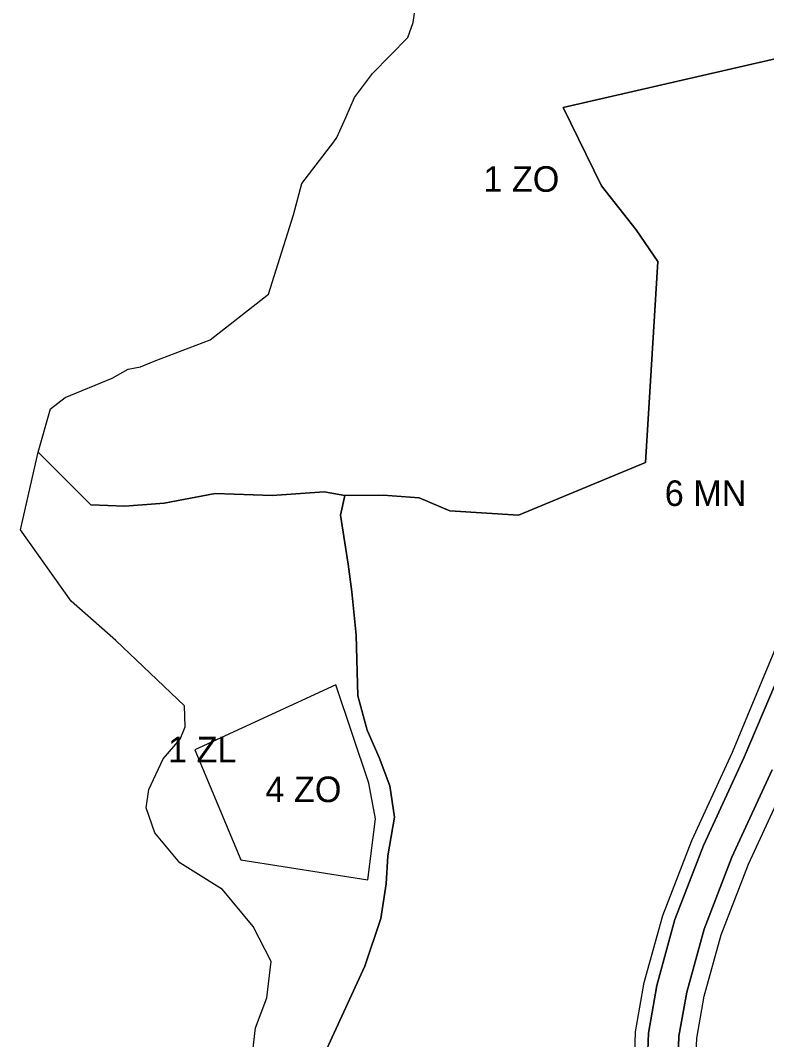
# Model space of a CAD drawing. Extents: x 7424258 to 7426021, y 5551671 to 5553193.
# Drawn here: x 7424719 to 7425010.8, y 5552254.6 to 5552653.2 of the extents above; entities that cross this region are included whole.
import ezdxf

# ---------------------------------------------------------------- set-up
doc = ezdxf.new("R2010")
doc.units = 0
for name, color, linetype in [('linie_rozgraniczajace', 7, 'Continuous'), ('linie_zabudowy_nieprzekraczalne', 7, 'Continuous'), ('oznaczenia_przeznaczen', 7, 'Continuous')]:
    doc.layers.add(name, color=color, linetype=linetype)

msp = doc.modelspace()

# ---------------------------------------------------------------- linework, layer by layer
at = {"layer": 'linie_rozgraniczajace'}
for points in [[(7425051.06, 5552646.66), (7424995.42, 5552633.88), (7424931.2, 5552619.13), (7424946.21, 5552588.55), (7424959.87, 5552571.29), (7424968.35, 5552558.94), (7424963.44, 5552480.3), (7424913.85, 5552459.68), (7424886.97, 5552461.47), (7424874.98, 5552466.54), (7424860.8, 5552467.57), (7424845.83, 5552467.4), (7424837.76, 5552468.8), (7424817.51, 5552467.42), (7424795.11, 5552468.2), (7424775.22, 5552464.46), (7424759.82, 5552463.2), (7424746.49, 5552463.77), (7424726, 5552484.37), (7424730.78, 5552501.26), (7424736.47, 5552505.78), (7424754.82, 5552513.35), (7424761.17, 5552516.77), (7424765.9, 5552517.79), (7424771.24, 5552520), (7424793.23, 5552528.28), (7424816.07, 5552546.19), (7424825.79, 5552577.17), (7424829.04, 5552589.49), (7424841.61, 5552605.76), (7424842.74, 5552607.38), (7424846.22, 5552615.24), (7424849.71, 5552623.09), (7424856.75, 5552632.4), (7424870.55, 5552646.47), (7424872.66, 5552652.39), (7424873.65, 5552659.77)], [(7424836.47, 5552245.91), (7424853.66, 5552283.41), (7424859.99, 5552302.04), (7424862.02, 5552315.51), (7424862.63, 5552326.5), (7424865.3, 5552341.64), (7424863.44, 5552353.82), (7424859.27, 5552364.91), (7424854.67, 5552375.64), (7424850.96, 5552389.13), (7424850.3, 5552412.81), (7424848.56, 5552429.74), (7424847.22, 5552440.55), (7424844.17, 5552459.66), (7424845.83, 5552467.4), (7424860.8, 5552467.57), (7424874.98, 5552466.54), (7424886.97, 5552461.47), (7424913.85, 5552459.68), (7424963.44, 5552480.3), (7424968.35, 5552558.94), (7424959.87, 5552571.29), (7424946.21, 5552588.55), (7424931.2, 5552619.13), (7424995.42, 5552633.88), (7425051.06, 5552646.66)], [(7424809.54, 5552246.79), (7424810.92, 5552259.2), (7424815.33, 5552270.93), (7424817.09, 5552285.18), (7424809.99, 5552298.89), (7424797.99, 5552313.35), (7424781.28, 5552323.8), (7424771.54, 5552335.48), (7424768.23, 5552345.3), (7424769.18, 5552352.42), (7424774.86, 5552364.48), (7424781.51, 5552372.14), (7424783.46, 5552376.91), (7424783.18, 5552385.11), (7424769.77, 5552397.94), (7424756.36, 5552410.77), (7424738.87, 5552426.09), (7424718.98, 5552453.98), (7424726, 5552484.37), (7424746.49, 5552463.77), (7424759.82, 5552463.2), (7424775.22, 5552464.46), (7424795.11, 5552468.2), (7424817.51, 5552467.42), (7424837.76, 5552468.8), (7424845.83, 5552467.4), (7424844.17, 5552459.66), (7424847.22, 5552440.55), (7424848.56, 5552429.74), (7424850.3, 5552412.81), (7424850.96, 5552389.13), (7424854.67, 5552375.64), (7424859.27, 5552364.91), (7424863.44, 5552353.82), (7424865.3, 5552341.64), (7424862.63, 5552326.5), (7424862.02, 5552315.51), (7424859.99, 5552302.04), (7424853.66, 5552283.41), (7424836.47, 5552245.91)], [(7424963.95, 5552240.26), (7424964.59, 5552257.19), (7424967.89, 5552275.82), (7424975, 5552301.6), (7424986.21, 5552330.58), (7425002.08, 5552365.14), (7425014.25, 5552393.94)], [(7425014.25, 5552393.94), (7425002.08, 5552365.14), (7424986.21, 5552330.58), (7424975, 5552301.6), (7424967.89, 5552275.82), (7424964.59, 5552257.19), (7424963.95, 5552240.26)], [(7425012.96, 5552360.1), (7424997.27, 5552325.91), (7424986.41, 5552297.84), (7424979.6, 5552273.17), (7424976.55, 5552255.92), (7424975.95, 5552239.91), (7424975.57, 5552222.89), (7424980.24, 5552190.48), (7424982.64, 5552180.39), (7424986.2, 5552167.56), (7424990.59, 5552152.55), (7424991.3, 5552148.61), (7424991.71, 5552144.98), (7424991.83, 5552139.15), (7424990.47, 5552133.05), (7424988.85, 5552128.42), (7424986.17, 5552122.7), (7424976.29, 5552104.66), (7424974.12, 5552098.87), (7424972.08, 5552090.57), (7424970.97, 5552083.52), (7424969.97, 5552061.31), (7424957.97, 5552061.6)], [(7424975.95, 5552239.91), (7424976.55, 5552255.92), (7424979.6, 5552273.17), (7424986.41, 5552297.84), (7424997.27, 5552325.91), (7425012.96, 5552360.1)]]:
    msp.add_lwpolyline(points, dxfattribs=at)
msp.add_lwpolyline([(7424787.23, 5552368.01), (7424805.18, 5552324.91), (7424854.86, 5552317.06), (7424857.91, 5552341.02), (7424855.28, 5552354.87), (7424842.3, 5552393.39)], close=True, dxfattribs=at)
msp.add_lwpolyline([(7424787.23, 5552368.01), (7424805.18, 5552324.91), (7424854.86, 5552317.06), (7424857.91, 5552341.02), (7424855.28, 5552354.87), (7424842.3, 5552393.39)], close=True, dxfattribs=at)
at = {"layer": 'linie_zabudowy_nieprzekraczalne'}
for points in [[(7424974.35, 5552139.25), (7424974.86, 5552141.92), (7424974.48, 5552146.11), (7424974.02, 5552148.64), (7424971.92, 5552155.83), (7424969.86, 5552162.91), (7424968.01, 5552169.54), (7424966.18, 5552176.15), (7424964.84, 5552181.75), (7424963.52, 5552187.29), (7424961.12, 5552203.96), (7424958.64, 5552222), (7424958.67, 5552227.64), (7424958.77, 5552231.99), (7424959.6, 5552257.72), (7424963, 5552276.92), (7424970.25, 5552303.17), (7424981.6, 5552332.53), (7424997.47, 5552367.09), (7425003.55, 5552381.47), (7425014.43, 5552407.8)], [(7424977.19, 5552066.06), (7424977.94, 5552082.81), (7424978.95, 5552089.19), (7424980.81, 5552096.8), (7424982.8, 5552102.06), (7424992.42, 5552119.53), (7424995.57, 5552126.27), (7424997.25, 5552131.23), (7424998.83, 5552139.52), (7424998.7, 5552145.49), (7424998.23, 5552149.63), (7424997.41, 5552154.15), (7424995.78, 5552159.74), (7424992.71, 5552170.26), (7424987.12, 5552191.79), (7424982.57, 5552223.26), (7424982.95, 5552239.7), (7424983.52, 5552255.17), (7424986.44, 5552271.63), (7424993.06, 5552295.63), (7425003.72, 5552323.19), (7425018.64, 5552355.47)]]:
    msp.add_lwpolyline(points, dxfattribs=at)

# ---------------------------------------------------------------- texts
at = {"layer": 'oznaczenia_przeznaczen'}
for s, p in [('1 ZO', (7424900.05, 5552586.18)), ('6 MN', (7424970.99, 5552463.31)), ('1 ZL', (7424776.75, 5552363.05)), ('4 ZO', (7424814.82, 5552347.51))]:
    msp.add_text(s, height=10, dxfattribs=at).set_placement(p)

doc.saveas('drawing.dxf')
